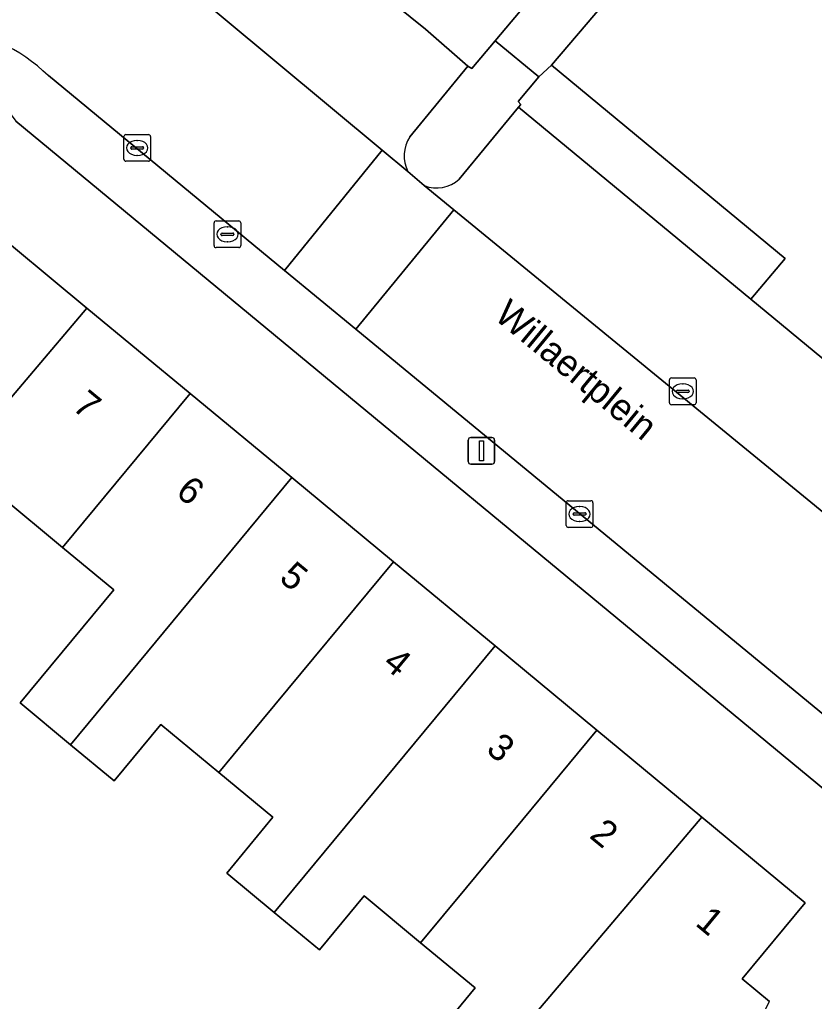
# Model space of a CAD drawing. Extents: x 159817 to 160765, y 380688 to 381638.
# Drawn here: x 160122.37 to 160152.14, y 381433.18 to 381469.95 of the extents above; entities that cross this region are included whole.
import ezdxf

# ---------------------------------------------------------------- set-up
doc = ezdxf.new("R2010")
doc.units = 0
for name, color, linetype in [('IMGEO_Brandkraan', 7, 'Continuous'), ('IMGEO_Erf', 7, 'Continuous'), ('IMGEO_Groenvoorziening', 7, 'Continuous'), ('IMGEO_Haag', 7, 'Continuous'), ('IMGEO_Kolk', 7, 'Continuous'), ('IMGEO_Lichtmast', 7, 'Continuous'), ('IMGEO_Openbare_ruimte_label', 7, 'Continuous'), ('IMGEO_Pand', 7, 'Continuous'), ('IMGEO_Pand_nummerreeks', 7, 'Continuous'), ('IMGEO_Parkeervlak_open', 7, 'Continuous'), ('IMGEO_Rijbaan_lokaal_open', 7, 'Continuous'), ('IMGEO_Voetpad_gesloten', 7, 'Continuous'), ('IMGEO_Voetpad_open', 7, 'Continuous')]:
    doc.layers.add(name, color=color, linetype=linetype)

msp = doc.modelspace()

# ---------------------------------------------------------------- linework, layer by layer
at = {"layer": 'IMGEO_Brandkraan'}
for p, q in [((160129.654, 381461.488), (160129.654, 381462.34)), ((160129.729, 381462.414), (160130.581, 381462.414)), ((160130.142, 381462.194), (160130.167, 381462.194)), ((160130.655, 381462.34), (160130.655, 381461.488)), ((160129.913, 381461.908), (160129.913, 381461.92)), ((160130.351, 381461.871), (160129.953, 381461.871)), ((160129.956, 381461.957), (160130.354, 381461.957)), ((160130.397, 381461.92), (160130.397, 381461.908)), ((160130.581, 381461.414), (160129.729, 381461.414)), ((160130.165, 381461.634), (160130.14, 381461.634))]:
    msp.add_line(p, q, dxfattribs=at)
for points in [[(160129.654, 381461.488), (160129.654, 381462.34)], [(160129.729, 381462.414), (160130.581, 381462.414)], [(160130.655, 381462.34), (160130.655, 381461.488)], [(160130.581, 381461.414), (160129.729, 381461.414)]]:
    msp.add_lwpolyline(points, dxfattribs=at)
for centre, radius, start, end in [((160129.731, 381462.338), 0.0765, 91.552, 178.448), ((160129.731, 381462.338), 0.0765, 91.552, 178.448), ((160130.579, 381462.338), 0.0765, 1.552, 88.448), ((160130.579, 381462.338), 0.0765, 1.552, 88.448), ((160129.953, 381461.917), 0.0403, 85.8775, 175.7526), ((160129.95, 381461.907), 0.0366, 178.938, 274.7102), ((160130.354, 381461.914), 0.043, 264.8664, 352.4533), ((160130.358, 381461.919), 0.0386, 1.7309, 96.639), ((160129.731, 381461.49), 0.0765, 181.552, 268.448), ((160129.731, 381461.49), 0.0765, 181.552, 268.448), ((160130.579, 381461.49), 0.0765, 271.552, 358.448), ((160130.579, 381461.49), 0.0765, 271.552, 358.448)]:
    msp.add_arc(centre, radius, start, end, dxfattribs=at)
for centre, major_axis, ratio, start_param, end_param in [((160130.141, 381461.914), (-0.387, 0.002), 0.722429, 4.712389, 7.853982), ((160130.166, 381461.914), (-0.39, 0.002), 0.717154, 1.570796, 4.712389)]:
    msp.add_ellipse(centre, major_axis=major_axis, ratio=ratio, start_param=start_param, end_param=end_param, dxfattribs=at)
at = {"layer": 'IMGEO_Erf'}
for points in [[(160147.119, 381416.719), (160155.458, 381434.407), (160156.601, 381436.871), (160156.303, 381437.977), (160122.231, 381466.144)], [(160120.791, 381462.547), (160124.893, 381459.15), (160128.756, 381455.951), (160132.565, 381452.796), (160136.372, 381449.644), (160140.181, 381446.489), (160143.989, 381443.336), (160147.927, 381440.075), (160151.796, 381436.871), (160149.436, 381434.021), (160150.464, 381433.17)], [(160137.746, 381431.636), (160139.437, 381433.679), (160137.393, 381435.371), (160135.278, 381437.123), (160133.606, 381435.103), (160131.912, 381436.505), (160130.129, 381437.981), (160131.859, 381440.07), (160129.833, 381441.747), (160127.658, 381443.548), (160125.911, 381441.438), (160124.279, 381442.79), (160122.389, 381444.355), (160125.898, 381448.592), (160123.979, 381450.181), (160121.666, 381452.096)]]:
    msp.add_lwpolyline(points, dxfattribs=at)
at = {"layer": 'IMGEO_Groenvoorziening'}
for points in [[(160157.199, 381485.941), (160156.852, 381485.447), (160148.71, 381475.795), (160142.292, 381468.244), (160151.047, 381461.01), (160149.766, 381459.479), (160152.71, 381457.046), (160153.546, 381458.031), (160157.867, 381454.278), (160157.114, 381453.406), (160158.383, 381452.357), (160159.598, 381451.877), (160160.915, 381461.353), (160162.671, 381463.549), (160164.428, 381464.866), (160167.246, 381466.544), (160171.443, 381473.914)], [(160145.397, 381476.452), (160142.913, 381479.241), (160142.527, 381479.647), (160135.22, 381471.513), (160137.58, 381469.594), (160139.165, 381468.211), (160139.317, 381468.118), (160140.189, 381469.158), (160145.532, 381475.513)]]:
    msp.add_lwpolyline(points, dxfattribs=at)
msp.add_lwpolyline([(160149.766, 381459.479), (160151.047, 381461.01), (160142.292, 381468.244), (160141.827, 381467.816), (160141.053, 381466.882), (160141.15, 381466.778), (160141.059, 381466.674)], close=True, dxfattribs=at)
at = {"layer": 'IMGEO_Haag'}
msp.add_lwpolyline([(160149.766, 381459.479), (160151.047, 381461.01), (160142.292, 381468.244), (160141.827, 381467.816), (160141.053, 381466.882), (160141.15, 381466.778), (160141.059, 381466.674)], close=True, dxfattribs=at)
at = {"layer": 'IMGEO_Kolk'}
for p, q in [((160126.274, 381464.723), (160126.274, 381465.575)), ((160126.349, 381465.649), (160127.201, 381465.649)), ((160126.762, 381465.429), (160126.787, 381465.429)), ((160127.275, 381465.575), (160127.275, 381464.723)), ((160126.533, 381465.143), (160126.533, 381465.155)), ((160126.971, 381465.106), (160126.573, 381465.106)), ((160126.576, 381465.192), (160126.974, 381465.192)), ((160127.017, 381465.155), (160127.017, 381465.143)), ((160126.785, 381464.869), (160126.76, 381464.869)), ((160127.201, 381464.649), (160126.349, 381464.649)), ((160146.713, 381455.603), (160146.713, 381456.455)), ((160146.788, 381456.529), (160147.64, 381456.529)), ((160147.201, 381456.309), (160147.226, 381456.309)), ((160147.714, 381456.455), (160147.714, 381455.603)), ((160146.972, 381456.023), (160146.972, 381456.035)), ((160147.41, 381455.986), (160147.012, 381455.986)), ((160147.015, 381456.072), (160147.413, 381456.072)), ((160147.456, 381456.035), (160147.456, 381456.023)), ((160147.64, 381455.529), (160146.788, 381455.529)), ((160147.224, 381455.749), (160147.199, 381455.749)), ((160142.849, 381451.005), (160142.849, 381451.857)), ((160142.924, 381451.931), (160143.776, 381451.931)), ((160143.85, 381451.857), (160143.85, 381451.005)), ((160143.108, 381451.425), (160143.108, 381451.437)), ((160143.151, 381451.474), (160143.549, 381451.474)), ((160143.337, 381451.711), (160143.362, 381451.711)), ((160143.592, 381451.437), (160143.592, 381451.425)), ((160143.546, 381451.388), (160143.148, 381451.388)), ((160143.36, 381451.151), (160143.335, 381451.151)), ((160143.776, 381450.931), (160142.924, 381450.931))]:
    msp.add_line(p, q, dxfattribs=at)
for points in [[(160126.274, 381464.723), (160126.274, 381465.575)], [(160126.349, 381465.649), (160127.201, 381465.649)], [(160127.275, 381465.575), (160127.275, 381464.723)], [(160127.201, 381464.649), (160126.349, 381464.649)], [(160146.713, 381455.603), (160146.713, 381456.455)], [(160146.788, 381456.529), (160147.64, 381456.529)], [(160147.714, 381456.455), (160147.714, 381455.603)], [(160147.64, 381455.529), (160146.788, 381455.529)], [(160142.849, 381451.005), (160142.849, 381451.857)], [(160142.924, 381451.931), (160143.776, 381451.931)], [(160143.85, 381451.857), (160143.85, 381451.005)], [(160143.776, 381450.931), (160142.924, 381450.931)]]:
    msp.add_lwpolyline(points, dxfattribs=at)
for centre, radius, start, end in [((160126.351, 381465.573), 0.0765, 91.552, 178.448), ((160126.351, 381465.573), 0.0765, 91.552, 178.448), ((160127.199, 381465.573), 0.0765, 1.552, 88.448), ((160127.199, 381465.573), 0.0765, 1.552, 88.448), ((160126.573, 381465.152), 0.0403, 85.8775, 175.7526), ((160126.57, 381465.142), 0.0366, 178.938, 274.7102), ((160126.974, 381465.149), 0.043, 264.8664, 352.4533), ((160126.978, 381465.154), 0.0386, 1.7309, 96.639), ((160126.351, 381464.725), 0.0765, 181.552, 268.448), ((160126.351, 381464.725), 0.0765, 181.552, 268.448), ((160127.199, 381464.725), 0.0765, 271.552, 358.448), ((160127.199, 381464.725), 0.0765, 271.552, 358.448), ((160146.79, 381456.453), 0.0765, 91.552, 178.448), ((160146.79, 381456.453), 0.0765, 91.552, 178.448), ((160147.638, 381456.453), 0.0765, 1.552, 88.448), ((160147.638, 381456.453), 0.0765, 1.552, 88.448), ((160147.012, 381456.032), 0.0403, 85.8775, 175.7526), ((160147.009, 381456.022), 0.0366, 178.938, 274.7102), ((160147.413, 381456.029), 0.043, 264.8664, 352.4533), ((160147.417, 381456.034), 0.0386, 1.7309, 96.639), ((160146.79, 381455.605), 0.0765, 181.552, 268.448), ((160146.79, 381455.605), 0.0765, 181.552, 268.448), ((160147.638, 381455.605), 0.0765, 271.552, 358.448), ((160147.638, 381455.605), 0.0765, 271.552, 358.448), ((160142.926, 381451.855), 0.0765, 91.552, 178.448), ((160142.926, 381451.855), 0.0765, 91.552, 178.448), ((160143.774, 381451.855), 0.0765, 1.552, 88.448), ((160143.774, 381451.855), 0.0765, 1.552, 88.448), ((160143.148, 381451.434), 0.0403, 85.8775, 175.7526), ((160143.553, 381451.436), 0.0386, 1.7309, 96.639), ((160143.145, 381451.424), 0.0366, 178.938, 274.7102), ((160143.549, 381451.431), 0.043, 264.8664, 352.4533), ((160142.926, 381451.007), 0.0765, 181.552, 268.448), ((160142.926, 381451.007), 0.0765, 181.552, 268.448), ((160143.774, 381451.007), 0.0765, 271.552, 358.448), ((160143.774, 381451.007), 0.0765, 271.552, 358.448)]:
    msp.add_arc(centre, radius, start, end, dxfattribs=at)
for centre, major_axis, ratio, start_param, end_param in [((160126.761, 381465.149), (-0.387, 0.002), 0.722429, 4.712389, 7.853982), ((160126.786, 381465.149), (-0.39, 0.002), 0.717154, 1.570796, 4.712389), ((160147.2, 381456.029), (-0.387, 0.002), 0.722429, 4.712389, 7.853982), ((160147.225, 381456.029), (-0.39, 0.002), 0.717154, 1.570796, 4.712389), ((160143.336, 381451.431), (-0.387, 0.002), 0.722429, 4.712389, 7.853982), ((160143.361, 381451.431), (-0.39, 0.002), 0.717154, 1.570796, 4.712389)]:
    msp.add_ellipse(centre, major_axis=major_axis, ratio=ratio, start_param=start_param, end_param=end_param, dxfattribs=at)
at = {"layer": 'IMGEO_Lichtmast'}
for p, q in [((160139.173, 381453.401), (160139.173, 381454.201)), ((160139.173, 381454.201), (160139.173, 381453.401)), ((160139.273, 381454.301), (160140.063, 381454.301)), ((160140.063, 381454.301), (160139.273, 381454.301)), ((160140.163, 381454.201), (160140.163, 381453.401)), ((160140.163, 381453.401), (160140.163, 381454.201)), ((160140.063, 381453.301), (160139.273, 381453.301)), ((160139.273, 381453.301), (160140.063, 381453.301))]:
    msp.add_line(p, q, dxfattribs=at)
msp.add_lwpolyline([(160139.593, 381454.176), (160139.743, 381454.176), (160139.743, 381453.426), (160139.593, 381453.426), (160139.593, 381454.176)], dxfattribs=at)
for centre, start, end in [((160139.273, 381454.201), 90, 180), ((160139.273, 381454.201), 90, 180), ((160140.063, 381454.201), 0, 90), ((160140.063, 381454.201), 360, 90), ((160139.273, 381453.401), 180, 270), ((160139.273, 381453.401), 180, 270), ((160140.063, 381453.401), 270, 0), ((160140.063, 381453.401), 270, 0)]:
    msp.add_arc(centre, 0.1, start, end, dxfattribs=at)
at = {"layer": 'IMGEO_Pand'}
for points in [[(160124.893, 381459.15), (160120.791, 381462.547), (160118.493, 381459.773), (160117.571, 381460.537), (160116.002, 381459.456), (160115.273, 381457.416), (160118.143, 381455.04), (160114.658, 381450.831), (160113.767, 381451.569), (160113.113, 381451.011), (160112.46, 381450.453), (160114.726, 381447.168), (160115.338, 381447.89), (160116.328, 381449.057)], [(160124.893, 381459.15), (160116.328, 381449.057), (160115.338, 381447.89), (160114.726, 381447.168), (160115.417, 381446.166), (160117.285, 381444.62), (160119.263, 381447.01), (160118.191, 381447.898), (160121.666, 381452.096), (160123.979, 381450.181), (160128.756, 381455.951)], [(160132.565, 381452.796), (160128.756, 381455.951), (160123.979, 381450.181), (160125.898, 381448.592), (160122.389, 381444.355), (160124.279, 381442.79)], [(160132.565, 381452.796), (160124.279, 381442.79), (160125.911, 381441.438), (160127.658, 381443.548), (160129.833, 381441.747), (160131.444, 381443.692), (160136.372, 381449.644)], [(160140.181, 381446.489), (160136.372, 381449.644), (160131.444, 381443.692), (160129.833, 381441.747), (160131.859, 381440.07), (160130.129, 381437.981), (160131.912, 381436.505)], [(160143.989, 381443.336), (160140.181, 381446.489), (160131.912, 381436.505), (160133.606, 381435.103), (160135.278, 381437.123), (160137.393, 381435.371), (160139.112, 381437.447)], [(160143.989, 381443.336), (160139.112, 381437.447), (160137.393, 381435.371), (160139.437, 381433.679), (160137.746, 381431.636), (160139.52, 381430.167), (160147.927, 381440.075)], [(160147.927, 381440.075), (160139.52, 381430.167), (160141.294, 381428.698), (160142.991, 381430.748), (160145.087, 381429.011), (160146.877, 381431.172), (160147.912, 381430.315), (160149.636, 381431.574), (160150.464, 381433.17), (160149.436, 381434.021), (160151.796, 381436.871)]]:
    msp.add_lwpolyline(points, close=True, dxfattribs=at)
at = {"layer": 'IMGEO_Parkeervlak_open'}
for points in [[(160127.985, 381471.712), (160135.947, 381465.067)], [(160137.58, 381469.594), (160135.22, 381471.513)], [(160139.165, 381468.211), (160137.58, 381469.594)], [(160136.992, 381465.566), (160139.165, 381468.211)], [(160149.766, 381459.479), (160141.059, 381466.674), (160138.833, 381463.982)], [(160135.947, 381465.067), (160136.913, 381464.261)], [(160137.528, 381463.734), (160138.635, 381462.828), (160156.221, 381448.434)], [(160156.174, 381449.649), (160158.383, 381452.357), (160157.114, 381453.406), (160152.71, 381457.046), (160149.766, 381459.479)]]:
    msp.add_lwpolyline(points, dxfattribs=at)
for centre, radius, start, end in [((160138.093, 381464.844), 1.316, 146.7549, 206.3166), ((160137.983, 381464.897), 1.249, 248.6211, 312.8991)]:
    msp.add_arc(centre, radius, start, end, dxfattribs=at)
at = {"layer": 'IMGEO_Rijbaan_lokaal_open'}
msp.add_lwpolyline([(160123.446, 381467.855), (160132.294, 381460.562), (160135.947, 381465.067), (160127.985, 381471.712)], dxfattribs=at)
for points in [[(160135.947, 381465.067), (160132.294, 381460.562), (160134.967, 381458.359), (160138.635, 381462.828), (160137.528, 381463.734), (160136.913, 381464.261)], [(160156.913, 381447.798), (160156.221, 381448.434), (160138.635, 381462.828), (160134.967, 381458.359), (160153.194, 381443.335)]]:
    msp.add_lwpolyline(points, close=True, dxfattribs=at)
msp.add_arc((160118.766, 381462.974), 6.762, 46.2062, 83.1065, dxfattribs=at)
at = {"layer": 'IMGEO_Voetpad_gesloten'}
msp.add_lwpolyline([(160158.742, 381489.467), (160158.904, 381489.65), (160158.123, 381490.504), (160156.084, 381488.109), (160148.041, 381478.719), (160145.532, 381475.513), (160140.189, 381469.158), (160141.827, 381467.816), (160142.292, 381468.244), (160148.71, 381475.795), (160156.852, 381485.447), (160157.199, 381485.941)], dxfattribs=at)
at = {"layer": 'IMGEO_Voetpad_open'}
for points in [[(160119.578, 381469.687), (160122.231, 381466.144), (160156.303, 381437.977), (160156.601, 381436.871), (160158.462, 381438.892), (160153.194, 381443.335), (160134.967, 381458.359)], [(160141.059, 381466.674), (160141.15, 381466.778), (160141.053, 381466.882), (160141.827, 381467.816), (160140.189, 381469.158), (160139.317, 381468.118), (160139.165, 381468.211), (160136.992, 381465.566)], [(160134.967, 381458.359), (160132.294, 381460.562), (160123.446, 381467.855)], [(160138.833, 381463.982), (160141.059, 381466.674)], [(160136.913, 381464.261), (160137.528, 381463.734)]]:
    msp.add_lwpolyline(points, dxfattribs=at)
for centre, radius, start, end in [((160118.766, 381462.974), 6.762, 46.2062, 83.1065), ((160138.093, 381464.844), 1.316, 146.7549, 206.3166), ((160137.983, 381464.897), 1.249, 248.6211, 312.8991)]:
    msp.add_arc(centre, radius, start, end, dxfattribs=at)

# ---------------------------------------------------------------- texts
at = {"layer": 'IMGEO_Openbare_ruimte_label'}
msp.add_text('Willaertplein', height=1, rotation=320.5171, dxfattribs=at).set_placement((160140.105, 381458.77))
at = {"layer": 'IMGEO_Pand_nummerreeks'}
for s, p in [('7', (160124.3, 381455.382)), ('6', (160128.175, 381452.173)), ('5', (160132.051, 381448.963)), ('4', (160135.927, 381445.754)), ('3', (160139.802, 381442.544)), ('2', (160143.677, 381439.336)), ('1', (160147.642, 381436.052))]:
    msp.add_text(s, height=1, rotation=320.371, dxfattribs=at).set_placement(p)

doc.saveas('drawing.dxf')
